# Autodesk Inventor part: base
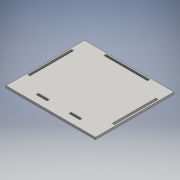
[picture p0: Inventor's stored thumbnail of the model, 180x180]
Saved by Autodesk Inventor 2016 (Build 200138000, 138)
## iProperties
Created: 2016-06
Part Number: base
Material: Genérico
Document SubType Name: Modeling
Designer: adm
Density: 1 g/cm^3
Appearance: Valor por defecto
Author: adm
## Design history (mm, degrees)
sketch "Boceto1"
  geometry: L1 (-61.5, -50)-(61.5, -50); L2 (61.5, -50)-(61.5, 50); L3 (61.5, 50)-(-61.5, 50); L4 (-61.5, 50)-(-61.5, -50); L5 (-61.5, -50)-(61.5, 50); L6 (61.5, -50)-(-61.5, 50); L7 (59.5, 30)-(59.5, -30); L8 (-59.5, -30)-(-59.5, 30); L9 (-56.5, 30)-(-56.5, -30); L10 (56.5, -30)-(56.5, 30); L11 (-59.5, -30)-(-56.5, -30); L12 (56.5, -30)-(59.5, -30); L13 (-59.5, 30)-(-56.5, 30); L14 (-30, 48)-(-30, 45); L15 (30, 45)-(-30, 45); L16 (-30, 48)-(30, 48); L17 (56.5, 30)-(59.5, 30); L18 (30, 48)-(30, 45); L19 (30, -45)-(30, -48); L20 (-30, -45)-(-30, -48); L21 (30, -48)-(-30, -48); L22 (-30, -45)-(30, -45); 1 further point
  constraints: 44 end point, 6 parallel, 3 perpendicular, 2 midpoint, 1 horizontal
  dimensions: "d0" = 100 distance of L2.end L1.end; "d1" = 123 distance of L2.end L3.end; "d12" = 60 distance between parallel lines of L19 L20; "d19" = 2 distance between parallel lines of L2 L7; "d20" = 3 distance between parallel lines of L7 L10; "d21" = 2 distance between parallel lines of L8 L4; "d22" = 3 distance between parallel lines of L8 L9
extrude "Extrusión1" new body sketch "Boceto1" distance "d8" = 3; taper "d9" = 0 deg
sketch "Boceto2"
  geometry: L1 (30, -45)-(-30, -45) reference; L2 (30, -48)-(-30, -48) reference; L3 (-15, -45)-(-15, -48); L4 (15, -45)-(15, -48); L5 (-15, -45)-(15, -45); L6 (-15, -48)-(15, -48); L7 (-61.5, -50)-(61.5, -50) reference; 1 further point
  constraints: 8 end point, 1 collinear, 1 parallel
extrude "Extrusión2" join sketch "Boceto2" distance "d15" = 3; taper "d16" = 0 deg
sketch "Boceto3"
  geometry: L1 (123, 0)-(123, 3) reference; L2 (0, 0)-(123, 0); L3 (123, 0)-(123, 3); L4 (123, 3)-(0, 3); L5 (0, 3)-(0, 0); 1 further point
  constraints: 8 end point, 2 parallel, 1 horizontal, 1 perpendicular
extrude "Extrusión3" join sketch "Boceto3" distance "d17" = 8; taper "d18" = 0 deg
node "Sólido1"
other parameters: "d2" = 2, "d3" = 3
